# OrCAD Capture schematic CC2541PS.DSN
size A4; title: CC2541 Postage Stamp; rev: 1.1
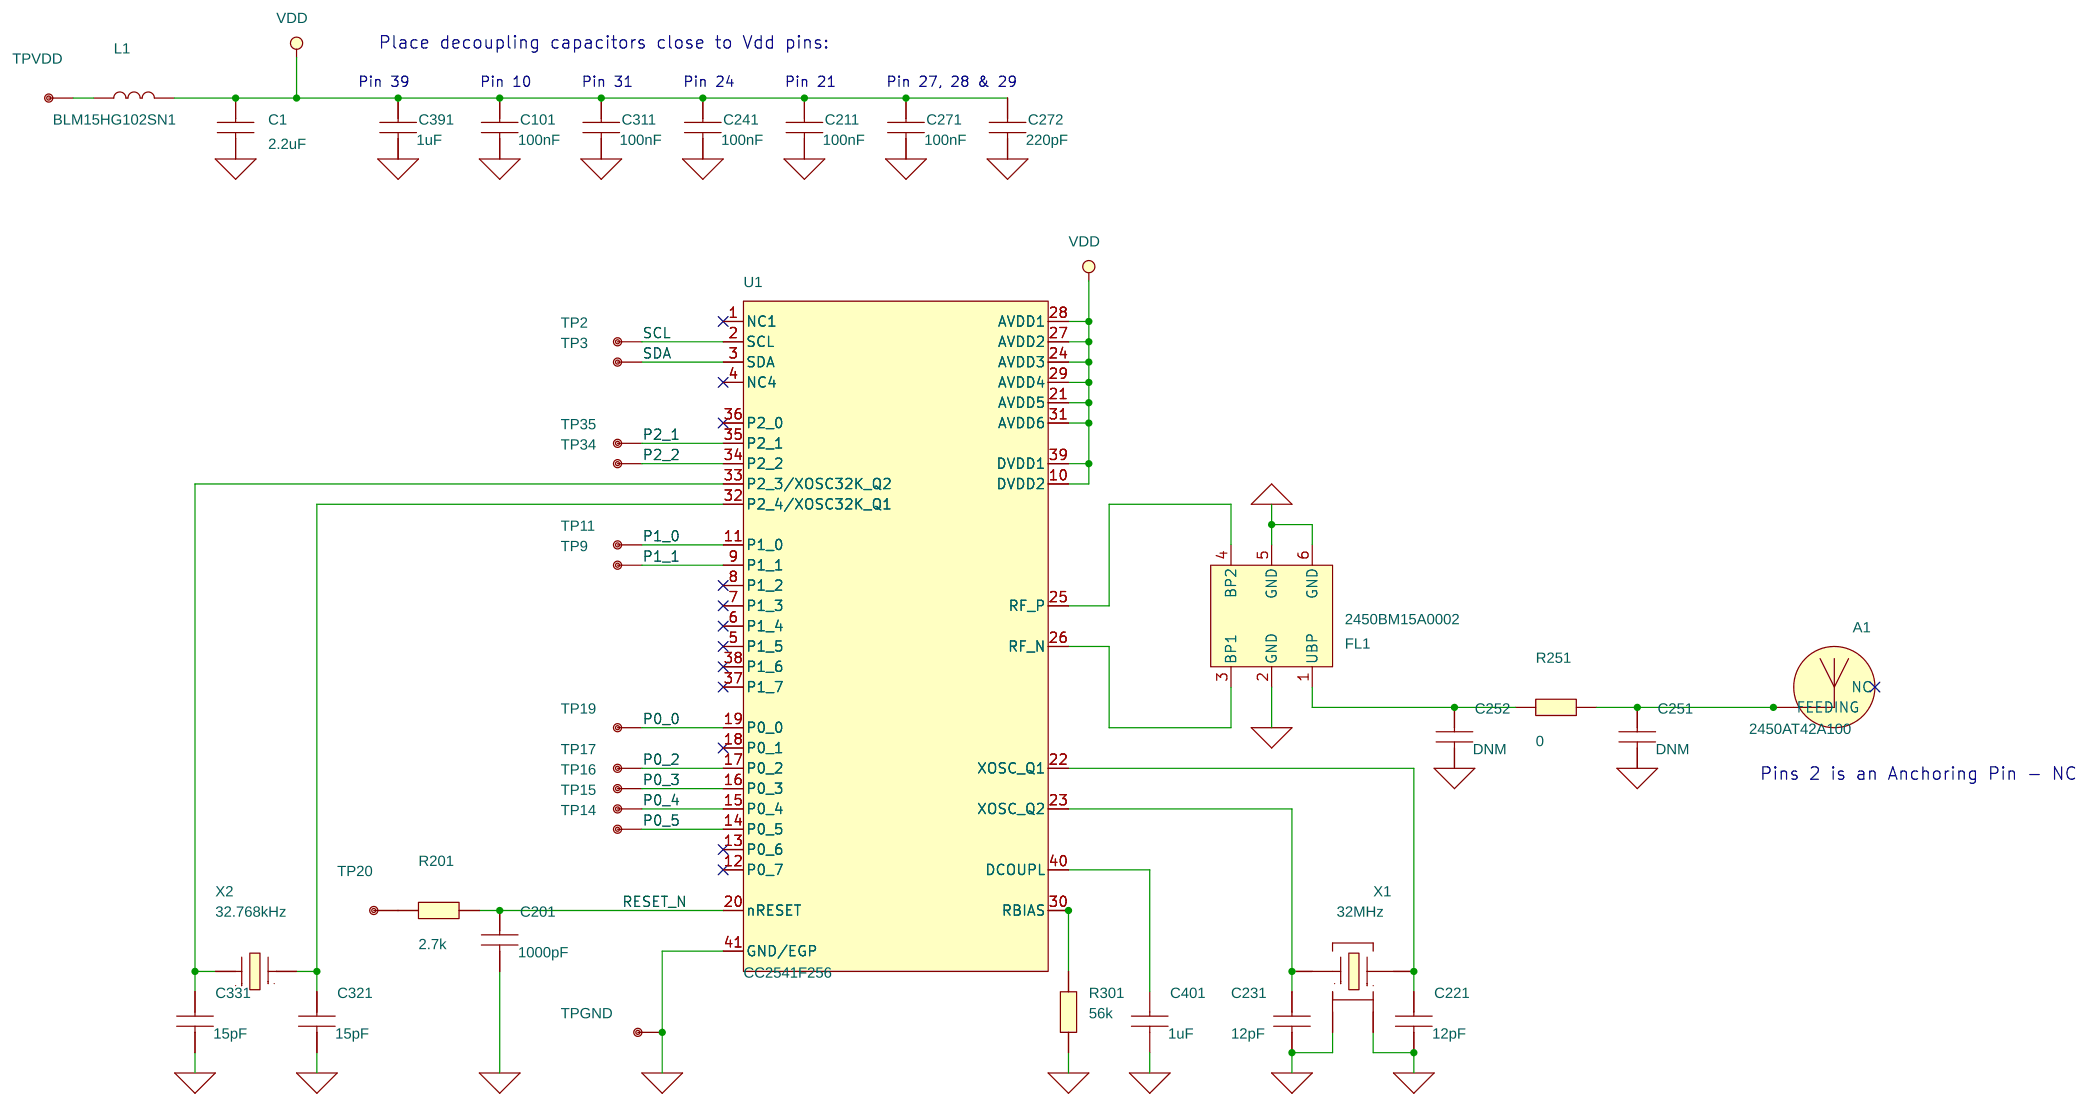
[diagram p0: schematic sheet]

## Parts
A1  2450AT42A100  [ANTENNA_2450AT42A100N]
C1  2.2uF  [CAPC1005X60L]
C101  100nF  [CAPC0603X35N]
C201  1000pF  [CAPC0603X35N]
C211  100nF  [CAPC0603X35N]
C221  12pF  [CAPC0603X35N]
C231  12pF  [CAPC0603X35N]
C241  100nF  [CAPC0603X35N]
C251  DNM  [CAPC0603X35N]
C252  DNM  [CAPC0603X35N]
C271  100nF  [CAPC0603X35N]
C272  220pF  [CAPC0603X35N]
C311  100nF  [CAPC0603X35N]
C321  15pF  [CAPC0603X35N]
C331  15pF  [CAPC0603X35N]
C391  1uF  [CAPC1005X60N]
C401  1uF  [CAPC1005X60N]
FL1  2450BM15A0002  [FIL_2450BM15A0002N]
L1  BLM15HG102SN1  [INDC1005X60L]
R201  2.7k  [RESC0603X35N]
R251  0  [RESC0603X35N]
R301  56k  [RESC0603X35N]
TP2  TP_0.5MM_PTH  [TP_90X50H]
TP3  TP_0.5MM_PTH  [TP_90X50H]
TP9  TP_0.5MM_PTH  [TP_90X50H]
TP11  TP_0.5MM_PTH  [TP_90X50H]
TP14  TP_0.5MM_PTH  [TP_90X50H]
TP15  TP_0.5MM_PTH  [TP_90X50H]
TP16  TP_0.5MM_PTH  [TP_90X50H]
TP17  TP_0.5MM_PTH  [TP_90X50H]
TP19  TP_0.5MM_PTH  [TP_90X50H]
TP20  TP_0.5MM_PTH  [TP_90X50H]
TP34  TP_0.5MM_PTH  [TP_90X50H]
TP35  TP_0.5MM_PTH  [TP_90X50H]
TPGND  TP_0.5MM_PTH  [TP_90X50H]
TPVDD  TP_0.5MM_PTH  [TP_90X50H]
U1  CC2541F256  [QFNFC50P600X600X100-41AL]
X1  32MHz  [XTAL_FA128L]
X2  32.768kHz  [XTAL_FC12MN]

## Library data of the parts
A1 = ANTENNA_2_PIN: MECHANIC, ANTENNA, HIGH FREQUENCY CERAMIC, 50R, 2.4GHz-2.5GHz, SMD; ALT_SYMBOLS: ANTENNA_2450AT42A100L,ANTENNA_2450AT42A100M; AutoDoc File: http://notefied-dynamic-precision.com/DB/Apps/Desktop/Item/Object.aspx?id=90550; Datasheet URL 2: http://www.johansontechnology.com/images/stories/ip/rf-antennas/2450AT42A100_v2.pdf; FPLIST: ANTENNA_2450AT42A100N,ANTENNA_2450AT42A100L,ANTENNA_2450AT42A100M; Frequency: 2.4GHz TO 2.5GHz; Impedance: 50; MPN: 2450AT42A100E; MPN Status: ACTIVE; Manufacturer: JOHANSON TECHNOLOGY; Max Oper Temp: +85DEGC; Min Oper Temp: -40DEGC; Mounting Type: SMD; NOTE Status: PREFERRED; Packing Size: 2000; Packing Type: TAPE_&_REEL; Part Number: 13-00494; Part Type: MECHANIC\ANTENNA; Revision: R001; RoHS Status: ROHS_COMPLIANT; Rtd Power: 3W
C1 = CAPACITOR: CAPACITOR, CERAMIC X5R, 2.2uF, 6.3V, -10%/+10%, -55DEGC/+85DEGC, 0402, SMD; ALT_SYMBOLS: CAPC1005X60L,CAPC1005X60M; AutoDoc File: http://notefied-dynamic-precision.com/DB/Apps/Desktop/Item/Object.aspx?id=86621; Budget Currency: USD; Budget Price: 0.0393; Datasheet URL 1: http://search.murata.co.jp/Ceramy/image/img/A01X/G101/ENG/GRM155R60J225KE95-01.pdf; Datasheet URL 2: http://search.murata.co.jp/Ceramy/image/img/A01X/G101/ENG/GRM155R60J225KE95-01.pdf; Dielectric Type: X5R; FPLIST: CAPC1005X60N,CAPC1005X60L,CAPC1005X60M; MPN: GRM155R60J225KE95D; MPN Status: ACTIVE; Manufacturer: MURATA; Max Oper Temp: +85DEGC; Max Tol: +10%; Min Oper Temp: -55DEGC; Min Tol: -10%; Mounting Type: SMD; NOTE Status: PREFERRED; Old Footprint: CAPC1005X60N; PCB Package: 0402; Packing Size: 10000; Packing Type: TAPE_&_REEL; Part Number: 02-04476; Part Type: CAPACITOR\CERAMIC\0402; Revision: R001; RoHS Status: ROHS_COMPLIANT; Rtd Voltage: 6.3V; WEIGHT: 0.0016g
C101 C211 C241 C271 C311 = CAPACITOR: CAPACITOR, CERAMIC X5R, 100nF, 6.3V, -10%/+10%, -55DEGC/+85DEGC, 0201, SMD; ALT_SYMBOLS: CAPC0603X35L,CAPC0603X35M; AutoDoc File: http://notefied-dynamic-precision.com/DB/Apps/Desktop/Item/Object.aspx?id=82835; Budget Currency: EUR; Budget Price: 0.073; Datasheet URL 1: N/A; Datasheet URL 2: http://www.avx.com/docs/Catalogs/cx5r.pdf; Definied Quality: INDUSTRIAL; Dielectric Type: X5R; FPLIST: CAPC0603X35N,CAPC0603X35L,CAPC0603X35M; Lead Time: 16; MPN: 02016D104KAT2A; MPN Status: ACTIVE; MSL: N/A; MTBF: N/A; MTBF Standard: N/A; Manufacturer: AVX; Max Oper Temp: +85DEGC; Max Tol: +10%; Min Oper Temp: -55DEGC; Min Tol: -10%; Mounting Type: SMD; NOTE Status: PREFERRED; PCB Package: 0201; Packing Size: 15000; Packing Type: TAPE_&_REEL; Part Number: 02-01686; Part Type: CAPACITOR\CERAMIC\0201; Revision: R002; RoHS Status: ROHS_COMPLIANT; Rtd Voltage: 6.3V; WEIGHT: N/A
C201 = CAPACITOR: CAPACITOR, CERAMIC, 1000pF, 10pF, X7R, 16V, 0201, SMD; ALT_SYMBOLS: CAPC0603X35L,CAPC0603X35M; AutoDoc File: http://notefied-dynamic-precision.com/DB/Apps/Desktop/Item/Object.aspx?id=49744; Budget Currency: EUR; Budget Price: 0.006; Datasheet URL 1: http://www.murata.com/products/catalog/pdf/c02e.pdf; Datasheet URL 2: http://www.murata.com/products/catalog/pdf/c02e.pdf; Dielectric Type: X7R; FPLIST: CAPC0603X35N,CAPC0603X35L,CAPC0603X35M; Lead Time: 52; LifeCycle Status: OBSOLETE; MPN: GRM033R71C102KD01D; MPN Status: ACTIVE; Manufacturer: MURATA; Max Oper Temp: +125DEGC; Min Oper Temp: -55DEGC; Min Tol: -10pF; Mounting Type: SMD; NOTE Status: PREFERRED; Old Footprint: CAPC0603X35N,0201; PCB Package: 0201; Packing Size: 15000; Packing Type: TAPE_&_REEL; Part Number: 02-00593; Part Type: CAPACITOR\CERAMIC\0201; Revision: R001; RoHS Status: ROHS_COMPLIANT; Rtd Voltage: 16V; WEIGHT: 0.00033g
C221 C231 = CAPACITOR: CAPACITOR, CERAMIC C0G/NP0, 12pF, 25V, -5%/+5%, -55DEGC/+125DEGC, 0201, SMD; ALT_SYMBOLS: CAPC0603X35L,CAPC0603X35M; AutoDoc File: http://notefied-dynamic-precision.com/DB/Apps/Desktop/Item/Object.aspx?id=85787; Budget Currency: EUR; Budget Price: 0.043; Datasheet URL 1: N/A; Datasheet URL 2: http://www.avx.com/docs/Catalogs/ccog.pdf; Definied Quality: INDUSTRIAL; Dielectric Type: C0G/NP0; FPLIST: CAPC0603X35N,CAPC0603X35L,CAPC0603X35M; Lead Time: 18; LifeCycle Status: ACTIVE; MPN: 02013A120JAT2A; MPN Status: ACTIVE; MSL: N/A; MTBF: N/A; MTBF Standard: N/A; Manufacturer: AVX; Max Oper Temp: +125DEGC; Max Tol: +5%; Min Oper Temp: -55DEGC; Min Tol: -5%; Mounting Type: SMD; NOTE Status: PREFERRED; PCB Package: 0201; Packing Size: 15000; Packing Type: TAPE_&_REEL; Part Number: 02-04277; Part Type: CAPACITOR\CERAMIC\0201; Revision: R001; RoHS Status: ROHS_COMPLIANT; Rtd Voltage: 25V; WEIGHT: N/A
C251 C252 = CAPACITOR: CAPACITOR, DO NOT MOUNT, 0201, SMD; ALT_SYMBOLS: CAPC0603X35L,CAPC0603X35N; AutoDoc File: https://notefied-dynamic-precision.com/NotefiedWebServices/AutoDocs.aspx?itemid=50471; FPLIST: CAPC0603X35N,CAPC0603X35L,CAPC0603X35N; Old Footprint: CAPC0603X35N,0201; Part Number: 02-01320; Part Type: CAPACITOR\CERAMIC\0201; Revision: R001
C272 = CAPACITOR: CAPACITOR, CERAMIC X7R, 220pF, 16V, -10%/+10%, -55DEGC/+125DEGC, 0201, SMD; ALT_SYMBOLS: CAPC0603X35L,CAPC0603X35M; AutoDoc File: http://notefied-dynamic-precision.com/DB/Apps/Desktop/Item/Object.aspx?id=85804; Budget Currency: EUR; Budget Price: 0.062; Datasheet URL 1: N/A; Datasheet URL 2: http://www.avx.com/docs/Catalogs/cx7r.pdf; Definied Quality: INDUSTRIAL; Dielectric Type: X7R; FPLIST: CAPC0603X35N,CAPC0603X35L,CAPC0603X35M; Lead Time: 18; LifeCycle Status: ACTIVE; MPN: 0201YC221KAT2A; MPN Status: ACTIVE; MSL: N/A; MTBF: N/A; MTBF Standard: N/A; Manufacturer: AVX; Max Oper Temp: +125DEGC; Max Tol: +10%; Min Oper Temp: -55DEGC; Min Tol: -10%; Mounting Type: SMD; NOTE Status: PREFERRED; PCB Package: 0201; Packing Size: 15000; Packing Type: TAPE_&_REEL; Part Number: 02-04294; Part Type: CAPACITOR\CERAMIC\0201; Revision: R001; RoHS Status: ROHS_COMPLIANT; Rtd Voltage: 16V; WEIGHT: N/A
C321 C331 = CAPACITOR: CAPACITOR, CERAMIC C0G/NP0, 15pF, 25V, -5%/+5%, -55DEGC/+125DEGC, 0201, SMD; ALT_SYMBOLS: CAPC0603X35L,CAPC0603X35M; AutoDoc File: http://notefied-dynamic-precision.com/DB/Apps/Desktop/Item/Object.aspx?id=85788; Budget Currency: EUR; Budget Price: 0.043; Datasheet URL 1: N/A; Datasheet URL 2: http://www.avx.com/docs/Catalogs/ccog.pdf; Definied Quality: INDUSTRIAL; Dielectric Type: C0G/NP0; FPLIST: CAPC0603X35N,CAPC0603X35L,CAPC0603X35M; Lead Time: 18; LifeCycle Status: ACTIVE; MPN: 02013A150JAT2A; MPN Status: ACTIVE; MSL: N/A; MTBF: N/A; MTBF Standard: N/A; Manufacturer: AVX; Max Oper Temp: +125DEGC; Max Tol: +5%; Min Oper Temp: -55DEGC; Min Tol: -5%; Mounting Type: SMD; NOTE Status: PREFERRED; PCB Package: 0201; Packing Size: 15000; Packing Type: TAPE_&_REEL; Part Number: 02-04278; Part Type: CAPACITOR\CERAMIC\0201; Revision: R001; RoHS Status: ROHS_COMPLIANT; Rtd Voltage: 25V; WEIGHT: N/A
C391 C401 = CAPACITOR: CAPACITOR, CERAMIC, 1uF, -20%+80%, Y5V, 6.3V, 0402, SMD; ALT_SYMBOLS: CAPC1005X60L,CAPC1005X60M; AutoDoc File: http://notefied-dynamic-precision.com/DB/Apps/Desktop/Item/Object.aspx?id=49715; Budget Currency: EUR; Budget Price: 0.013; Datasheet URL 1: http://search.murata.co.jp/Ceramy/image/img/A01X/G101/ENG/GRM155F50J105ZE01-01.pdf; Datasheet URL 2: http://search.murata.co.jp/Ceramy/image/img/A01X/G101/ENG/GRM155F50J105ZE01-01.pdf; Dielectric Type: Y5V; FPLIST: CAPC1005X60N,CAPC1005X60L,CAPC1005X60M; Lead Time: 10; LifeCycle Status: GROWTH; MPN: GRM155F50J105ZE01D; MPN Status: ACTIVE; Manufacturer: MURATA; Max Oper Temp: +125DEGC; Min Oper Temp: -55DEGC; Min Tol: -20%; Mounting Type: SMD; NOTE Status: PREFERRED; Old Footprint: CAPC1005X60N,0402; PCB Package: 0402; Packing Size: 10000; Packing Type: TAPE_&_REEL; Part Number: 02-00564; Part Type: CAPACITOR\CERAMIC\0402; Revision: R001; RoHS Status: ROHS_COMPLIANT; Rtd Voltage: 6.3V; WEIGHT: 0.0016g
FL1 = FILTER_LFB_6PIN: FILTER, FILTER BALUN, 2400MHz TO 2500MHz, -40DEGC/+125DEGC, 0805, SMD; ALT_SYMBOLS: FIL_2450BM15A0002L,FIL_2450BM15A0002M; AutoDoc File: http://notefied-dynamic-precision.com/DB/Apps/Desktop/Item/Object.aspx?id=89174; Budget Currency: USD; Budget Price: 0.255; Datasheet URL 2: http://www.johansontechnology.com/images/stories/ip/baluns/Balun_Filter_Matched_2450BM15A0002_v12.pdf; FPLIST: FIL_2450BM15A0002N,FIL_2450BM15A0002L,FIL_2450BM15A0002M; Frequency: 2400MHz TO 2500MHz; Impedance: 50; MPN: 2450BM15A0002E; MPN Status: ACTIVE; Manufacturer: JOHANSON TECHNOLOGY; Max Oper Temp: +125DEGC; Min Oper Temp: -40DEGC; Mounting Type: SMD; NOTE Status: PREFERRED; PCB Package: 0805; Packing Size: 4000; Packing Type: TAPE_&_REEL; Part Number: 04-00532; Part Type: FILTER\OTHER; Revision: R001; RoHS Status: ROHS_COMPLIANT; Rtd Power: 2W
L1 = INDUCTOR: FILTER, INDUCTOR TYPE, 1000OHM@100MHZ, 25%,250mA, 0402, SMD; ALT_SYMBOLS: INDC1005X60L,INDC1005X60M; AutoDoc File: http://notefied-dynamic-precision.com/DB/Apps/Desktop/Item/Object.aspx?id=15260; Budget Currency: EUR; Budget Price: 0.081; Datasheet URL 1: http://search.murata.co.jp/Ceramy/image/img/PDF/ENG/L0110S0101BLM15H.pdf; Datasheet URL 2: http://search.murata.co.jp/Ceramy/image/img/PDF/ENG/L0110S0101BLM15H.pdf; FPLIST: INDC1005X60N,INDC1005X60L,INDC1005X60M; Lead Time: 7; LifeCycle Status: ACTIVE; MPN: BLM15HG102SN1D; MPN Status: ACTIVE; Manufacturer: MURATA; Max Oper Temp: +125DEGC; Min Oper Temp: -55DEGC; Min Tol: -25%; Mounting Type: SMD; NOTE Status: PREFERRED; Old Footprint: INDC1005X60N,0402; PCB Package: 0402; Packing Size: 10000; Packing Type: TAPE_&_REEL; Part Number: 04-00032; Part Type: FILTER\EMI\0402; Revision: R001; RoHS Status: ROHS_COMPLIANT; Rtd Current: 0.25A; WEIGHT: 0.001g
R201 = RESISTOR: RESISTOR, THICK FILM, 2K7, -1%/+1%, 0.05W, 30V, -55DEGC/+125DEGC, 0201, SMD; ALT_SYMBOLS: RESC0603X35L,RESC0603X35M; AutoDoc File: http://notefied-dynamic-precision.com/DB/Apps/Desktop/Item/Object.aspx?id=58881; Budget Currency: EUR; Budget Price: 0.045; Datasheet URL 1: http://www.vishay.com/docs/20035/dcrcwe3.pdf; Datasheet URL 2: http://www.vishay.com/docs/20052/crcw0201e3.pdf; Definied Quality: COMMERCIAL; FPLIST: RESC0603X35N,RESC0603X35L,RESC0603X35M; Lead Time: 9; LifeCycle Status: ACTIVE; MPN: CRCW02012K70FKED; MPN Status: ACTIVE; MSL: 1; MTBF: 1.00*10^10; MTBF Standard: CL=90%; Manufacturer: VISHAY DALE; Max Oper Temp: +155DEGC; Max TC: +100PPM/DEGC; Max Tol: +1%; Min Oper Temp: -55DEGC; Min TC: -100PPM/DEGC; Min Tol: -1%; Mounting Type: SMD; NOTE Status: PREFERRED; Old Footprint: RESC0603X35N,0201; PCB Package: 0201; Packing Size: 10000; Packing Type: TAPE_&_REEL; Part Number: 01-04074; Part Type: RESISTOR\0201\PRECISION; Resistor Type: THICK FILM; Revision: R001; RoHS Status: ROHS_COMPLIANT; Rtd Power: 0.05W; Rtd Voltage: 30V; WEIGHT: 0.00017g
R251 = RESISTOR: RESISTOR, THICK FILM, 0R, -55DEGC/+125DEGC, 0201, SMD; ALT_SYMBOLS: RESC0603X35L,RESC0603X35M; AutoDoc File: http://notefied-dynamic-precision.com/DB/Apps/Desktop/Item/Object.aspx?id=58850; Budget Currency: EUR; Budget Price: 0.033; Datasheet URL 2: http://www.vishay.com/docs/20052/crcw0201e3.pdf; Definied Quality: COMMERCIAL; FPLIST: RESC0603X35N,RESC0603X35L,RESC0603X35M; Lead Time: 9; MPN: CRCW02010000Z0ED; MPN Status: ACTIVE; MSL: 1; MTBF: 1.00*10^10; MTBF Standard: CL=90%; Manufacturer: VISHAY; Max Oper Temp: +155DEGC; Min Oper Temp: -55DEGC; Mounting Type: SMD; NOTE Status: PREFERRED; Old Footprint: RESC0603X35N,0201; PCB Package: 0201; Packing Size: 10000; Packing Type: TAPE_&_REEL; Part Number: 01-04043; Part Type: RESISTOR\0201; Resistor Type: THICK FILM; Revision: R001; WEIGHT: 0.00017g
R301 = RESISTOR: RESISTOR, THICK FILM, 56K, -1%/+1%, 0.05W, 30V, -55DEGC/+125DEGC, 0201, SMD; ALT_SYMBOLS: RESC0603X35L,RESC0603X35M; AutoDoc File: http://notefied-dynamic-precision.com/DB/Apps/Desktop/Item/Object.aspx?id=58907; Budget Currency: EUR; Budget Price: 0.045; Datasheet URL 1: http://www.vishay.com/docs/20035/dcrcwe3.pdf; Datasheet URL 2: http://www.vishay.com/docs/20052/crcw0201e3.pdf; Definied Quality: COMMERCIAL; FPLIST: RESC0603X35N,RESC0603X35L,RESC0603X35M; Lead Time: 9; LifeCycle Status: ACTIVE; MPN: CRCW020156K0FKED; MPN Status: ACTIVE; MSL: 1; MTBF: 1.00*10^10; MTBF Standard: CL=90%; Manufacturer: VISHAY DALE; Max Oper Temp: +155DEGC; Max TC: +100PPM/DEGC; Max Tol: +1%; Min Oper Temp: -55DEGC; Min TC: -100PPM/DEGC; Min Tol: -1%; Mounting Type: SMD; NOTE Status: PREFERRED; Old Footprint: RESC0603X35N,0201; PCB Package: 0201; Packing Size: 10000; Packing Type: TAPE_&_REEL; Part Number: 01-04100; Part Type: RESISTOR\0201\PRECISION; Resistor Type: THICK FILM; Revision: R001; RoHS Status: ROHS_COMPLIANT; Rtd Power: 0.05W; Rtd Voltage: 30V; WEIGHT: 0.00017g
TP2 TP3 TP9 TP11 TP14-TP17 TP19 TP20 TP34 TP35 TPGND TPVDD = TP_LONGPIN: TESTPOINT, 0.5MM HOLE, PTH; AutoDoc File: https://notefied-dynamic-precision.com/NotefiedWebServices/AutoDocs.aspx?itemid=57983; FPLIST: TP_90X50H,; Part Number: 19-00199; Part Type: NON_COMPONENT\TEST_POINT; Revision: R000
U1 = IC_RF_CC2541_QFN40_V2: IC, DIGITAL WIRELESS, 2.4-GHz BLUETOOTH® LOW ENERGY AND PRIOPRIETARY SYSTEM-ON-CHIP, 256 KB, 2V TO 3.6V, VQFN40, SMD; ALT_SYMBOLS: QFNFC50P600X600X100-41L,QFNFC50P600X600X100-41M,QFNFC50P600X600X100-41AL,QFNFC50P600X600X100-41AM; AutoDoc File: http://notefied-dynamic-precision.com/DB/Apps/Desktop/Item/Object.aspx?id=87335; Budget Currency: USD; Budget Price: 2.00; Datasheet URL 1: N/A; Datasheet URL 2: http://www.ti.com/lit/ds/symlink/cc2541.pdf; Definied Quality: INDUSTRIAL; Esd Level: N/A; FPLIST: QFNFC50P600X600X100-41N,QFNFC50P600X600X100-41AN,QFNFC50P600X600X100-41L,QFNFC50P600X600X100-41M,QFNFC50P600X600X100-41AL,QFNFC50P600X600X100-41AM; Last Time Buy: N/A; Lead Time: 10; MPN: CC2541F256RHAR; MPN Status: ACTIVE; MSL: 3; MTBF: 3.77*10^8; MTBF Standard: CL=60%,Td=55degC,Ea=0.7eV,Ts=125degC; Manufacturer: TEXAS INSTRUMENTS; Max Oper Temp: +85DEGC; Min Oper Temp: -40DEGC; Mounting Type: SMD; NOTE Status: PREFERRED; Old Footprint: QFNFC50P600X600X100-41N,QFNFC50P600X600X100-41AN; PCB Package: VQFN40; Packing Size: 2500; Packing Type: TAPE_&_REEL; Part Number: 18-28143; Part Type: IC\DIGITAL\LOGIC\TRANSCEIVER; Revision: R003; RoHS Status: ROHS_COMPLIANT; Rtd Voltage: 2V TO 3.6V; WEIGHT: 0.1017g
X1 = XTAL_4: CRYSTAL, OSCILATOR, 32MHz, 10pF, -10PPM/+10PPM, -40DEGC/+85DEGC, SMD; ALT_SYMBOLS: XTAL_FA128L,XTAL_FA128M; AutoDoc File: http://notefied-dynamic-precision.com/DB/Apps/Desktop/Item/Object.aspx?id=85460; Capacitance: 10pF; Datasheet URL 1: http://www.epsontoyocom.co.jp/english/product/Crystal/set02/fa128/index.html; Datasheet URL 2: http://ndap3-net.ebz.epson.co.jp/w/www/PDFS/epdoc_qd.nsf/85a4e2c523a1f89349257068002f9e30/255cb2884010a1f9492571f0004c7d72/$FILE/FA-128_E107.pdf; FPLIST: XTAL_FA128N,XTAL_FA128L,XTAL_FA128M; MPN: FA-128 32MHz 10pF 10PPM; MPN Status: ACTIVE; Manufacturer: Epson Toyocom; Max Oper Temp: +85DEGC; Max Tol: +10PPM; Min Oper Temp: -40DEGC; Min Tol: -10PPM; Mounting Type: SMD; NOTE Status: PREFERRED; Old Footprint: XTAL_FA128N; PCB Package: SMD; Part Number: 12-00422; Part Type: CRYSTAL\OSCILLATOR\MEMS; Revision: R001; RoHS Status: ROHS_COMPLIANT
X2 = XTAL: CRYSTAL, OSCILATOR, 32.768kHz, -20PPM/ + 20PPM, -40DEGC/ +85DEGC, 12.5pF, SMD; ALT_SYMBOLS: XTAL_FC12ML,XTAL_FC12MM; AutoDoc File: http://notefied-dynamic-precision.com/DB/Apps/Desktop/Item/Object.aspx?id=85632; Budget Currency: EUR; Budget Price: 1.16; Capacitance: 12.5pF; Datasheet URL 1: http://www.eea.epson.com/portal/pls/portal/docs/1/1525528.PDF; Datasheet URL 2: http://www.eea.epson.com/portal/pls/portal/docs/1/1525509.PDF; Definied Quality: INDUSTRIAL; Esd Level: N/A; FPLIST: XTAL_FC12MN,XTAL_FC12ML,XTAL_FC12MM; Last Time Buy: N/A; Lead Time: 16; MPN: FC-12M 32.7680KA-A3; MPN Status: ACTIVE; MSL: N/A; MTBF: N/A; MTBF Standard: N/A; Manufacturer: EPSON; Max Oper Temp: +85DEGC; Max Tol: +20PPM; Min Oper Temp: -40DEGC; Min Tol: -20PPM; Mounting Type: SMD; NOTE Status: PREFERRED; Packing Size: 250; Packing Type: TAPE_&_REEL; Part Number: 12-00430; Part Type: CRYSTAL\OSCILLATOR\MEMS; Revision: R001; RoHS Status: ROHS_COMPLIANT; WEIGHT: N/A

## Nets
GND_SIGNAL: C1.2 C101.2 C201.2 C211.2 C221.2 C231.2 C241.2 C251.2 C252.2 C271.2 C272.2 C311.2 C321.2 C331.2 C391.2 C401.2 FL1.2(GND) FL1.5(GND) FL1.6(GND) R301.1 TPGND.1 U1.41(GND/EGP) X1.2 X1.4
VDD: C1.1 C101.1 C211.1 C241.1 C271.1 C272.1 C311.1 C391.1 L1.2 U1.10(DVDD2) U1.21(AVDD5) U1.24(AVDD3) U1.27(AVDD2) U1.28(AVDD1) U1.29(AVDD4) U1.31(AVDD6) U1.39(DVDD1)
P0_0: TP19.1 U1.19(P0_0)
P0_2: TP17.1 U1.17(P0_2)
P0_3: TP16.1 U1.16(P0_3)
P0_4: TP15.1 U1.15(P0_4)
P0_5: TP14.1 U1.14(P0_5)
P1_0: TP11.1 U1.11(P1_0)
P1_1: TP9.1 U1.9(P1_1)
P2_1: TP35.1 U1.35(P2_1)
P2_2: TP34.1 U1.34(P2_2)
RESET_N: C201.1 R201.1 U1.20(nRESET)
SCL: TP2.1 U1.2(SCL)
SDA: TP3.1 U1.3(SDA)
N173251: L1.1 TPVDD.1
N231514: C331.1 U1.33(P2_3/XOSC32K_Q2) X2.1
N231518: C321.1 U1.32(P2_4/XOSC32K_Q1) X2.2
N239349: FL1.4(BP2) U1.25(RF_P)
N239359: FL1.3(BP1) U1.26(RF_N)
N239704: C401.1 U1.40(DCOUPL)
N239709: R301.2 U1.30(RBIAS)
N249929: A1.1(FEEDING) C251.1 R251.1
N252810: C231.1 U1.23(XOSC_Q2) X1.3
N252820: C221.1 U1.22(XOSC_Q1) X1.1
N256510: C252.1 FL1.1(UBP) R251.2
N263145: R201.2 TP20.1

Not connected (* = marked no-connect by the designer): A1 2(NC)*; U1 1(NC1)* 4(NC4)* 5(P1)* 6(P1_4)* 7(P1_3)* 8(P1_2)* 12(P0_7)* 13(P0_6)* 18(P0_1)* 36(P2_0)* 37(P1_7)* 38(P1_6)*

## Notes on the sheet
- Place decoupling capacitors close to Vdd pins:
- Pin 39
- Pin 10
- Pin 31
- Pin 24
- Pin 21
- Pin 27, 28 & 29
- Pins 2 is an Anchoring Pin - NC
